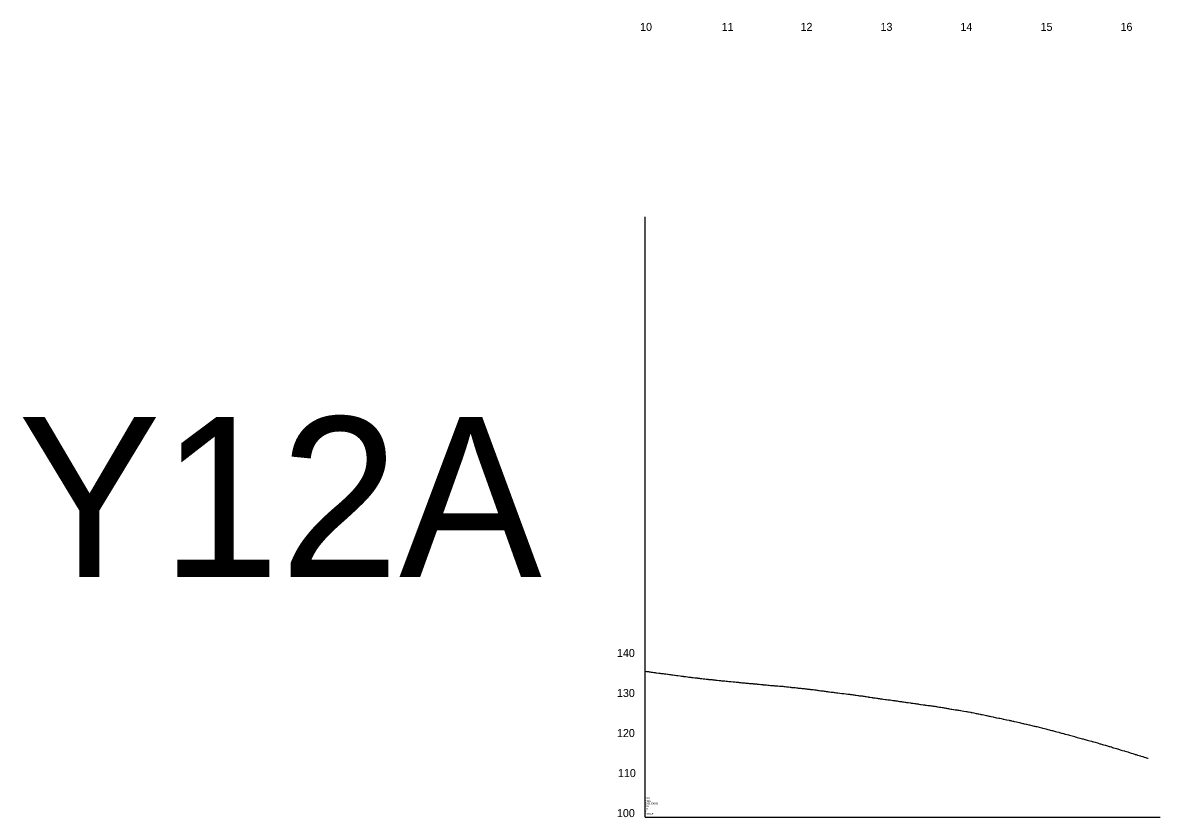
# Model space of a CAD drawing. Extents: x 1778432 to 1784301, y 601022 to 621789.
# Drawn here: x 1779365 to 1780786, y 605039 to 606032 of the extents above; entities that cross this region are included whole.
import ezdxf

# ---------------------------------------------------------------- set-up
doc = ezdxf.new("R2010")
doc.units = 0
for name, color, linetype in [('Exist Profile Cell', 7, 'Continuous'), ('Exist Vertical Profile Ground Line', 7, 'Continuous'), ('Exist Vertical Profile Horizontal Axis Label Major', 7, 'Continuous'), ('Exist Vertical Profile Vertical Axis Label', 7, 'Continuous'), ('Prop PFL Text', 7, 'Continuous')]:
    doc.layers.add(name, color=color, linetype=linetype)

msp = doc.modelspace()

# ---------------------------------------------------------------- linework, layer by layer
at = {"layer": 'Exist Profile Cell'}
for q in [(1780143, 605789.2), (1780786.2, 605039.2), (1780143, 605039.2)]:
    msp.add_line((1780143, 605039.2), q, dxfattribs=at)
at = {"layer": 'Exist Vertical Profile Ground Line'}
msp.add_lwpolyline([(1780143, 605221.6), (1780144.3, 605221.4), (1780145.2, 605221.3), (1780146.8, 605221.1), (1780147.9, 605220.9), (1780149.1, 605220.8), (1780150.2, 605220.6), (1780150.8, 605220.5), (1780151.9, 605220.4), (1780153.5, 605220.2), (1780154.2, 605220.1), (1780155.3, 605219.9), (1780156.2, 605219.8), (1780157.1, 605219.7), (1780159.7, 605219.3), (1780161.4, 605219.1), (1780162.4, 605219), (1780163.1, 605218.9), (1780164.2, 605218.8), (1780164.6, 605218.7), (1780165.3, 605218.6), (1780166.6, 605218.4), (1780168.6, 605218.2), (1780170.8, 605217.8), (1780171.4, 605217.8), (1780173.1, 605217.6), (1780173.9, 605217.4), (1780174.4, 605217.4), (1780175.7, 605217.2), (1780177.5, 605217), (1780179.3, 605216.7), (1780180.5, 605216.6), (1780182, 605216.4), (1780183.2, 605216.2), (1780183.5, 605216.2), (1780186.5, 605215.8), (1780188.3, 605215.6), (1780189.5, 605215.4), (1780190.1, 605215.3), (1780190.9, 605215.2), (1780191.9, 605215.1), (1780192.5, 605215), (1780193.8, 605214.9), (1780195.6, 605214.6), (1780197.3, 605214.4), (1780198.6, 605214.3), (1780199.4, 605214.2), (1780199.8, 605214.2), (1780200.9, 605214), (1780201.6, 605214), (1780202.7, 605213.8), (1780204.9, 605213.5), (1780206.3, 605213.3), (1780207.7, 605213.2), (1780208.1, 605213.1), (1780208.7, 605213.1), (1780209.9, 605212.9), (1780210.7, 605212.8), (1780211.7, 605212.6), (1780213.1, 605212.5), (1780213.7, 605212.4), (1780215.3, 605212.2), (1780216, 605212.1), (1780216.8, 605212.1), (1780217.1, 605212.1), (1780217.5, 605212), (1780218.9, 605211.8), (1780219.8, 605211.7), (1780220.7, 605211.7), (1780221.6, 605211.6), (1780221.9, 605211.5), (1780222.5, 605211.5), (1780222.8, 605211.4), (1780225, 605211.2), (1780225.9, 605211.1), (1780226.3, 605211.1), (1780227.2, 605211), (1780227.8, 605210.9), (1780228.9, 605210.8), (1780229.7, 605210.7), (1780230.7, 605210.6), (1780232, 605210.5), (1780232.7, 605210.4), (1780235.1, 605210.2), (1780236.8, 605210), (1780238.3, 605209.8), (1780239.5, 605209.7), (1780241.1, 605209.6), (1780242.2, 605209.5), (1780244.1, 605209.3), (1780245.8, 605209.1), (1780247.2, 605209), (1780247.6, 605208.9), (1780248.3, 605208.9), (1780249.4, 605208.7), (1780250.2, 605208.7), (1780252.6, 605208.4), (1780253.3, 605208.3), (1780255, 605208.2), (1780256.6, 605208), (1780256.9, 605208), (1780259.4, 605207.8), (1780260.1, 605207.7), (1780260.5, 605207.7), (1780261.2, 605207.6), (1780261.9, 605207.5), (1780262.4, 605207.4), (1780263.7, 605207.3), (1780265.6, 605207.1), (1780266.1, 605207.1), (1780267.3, 605207), (1780268.5, 605206.9), (1780269.1, 605206.8), (1780270, 605206.7), (1780270.9, 605206.6), (1780271.6, 605206.6), (1780272.7, 605206.5), (1780274.7, 605206.3), (1780276.3, 605206.2), (1780277.2, 605206.1), (1780277.7, 605206), (1780278.6, 605205.9), (1780279.9, 605205.8), (1780280.8, 605205.7), (1780281.7, 605205.7), (1780282.9, 605205.5), (1780283.5, 605205.4), (1780283.9, 605205.4), (1780285.3, 605205.3), (1780287.2, 605205.1), (1780288.3, 605205), (1780288.9, 605205), (1780290, 605204.9), (1780290.4, 605204.8), (1780291.5, 605204.7), (1780292.4, 605204.6), (1780293.1, 605204.6), (1780293.9, 605204.5), (1780294.2, 605204.5), (1780296.1, 605204.3), (1780297.8, 605204.1), (1780299.5, 605203.9), (1780300.1, 605203.9), (1780302.3, 605203.7), (1780303.4, 605203.6), (1780304.4, 605203.4), (1780305, 605203.4), (1780305.4, 605203.4), (1780306.6, 605203.3), (1780308.7, 605203.2), (1780310.6, 605203.1), (1780311.6, 605203), (1780312, 605203), (1780312.9, 605202.9), (1780313.9, 605202.8), (1780314.6, 605202.8), (1780316.1, 605202.6), (1780317.7, 605202.4), (1780319.2, 605202.3), (1780320.7, 605202.1), (1780321.7, 605202), (1780323.9, 605201.7), (1780324.6, 605201.6), (1780325.7, 605201.5), (1780326.5, 605201.5), (1780327.3, 605201.4), (1780327.6, 605201.3), (1780328.9, 605201.2), (1780330.1, 605201.1), (1780332, 605200.9), (1780332.8, 605200.8), (1780333.1, 605200.7), (1780333.9, 605200.6), (1780334.3, 605200.6), (1780335.4, 605200.5), (1780336.3, 605200.4), (1780337.1, 605200.3), (1780338.5, 605200.2), (1780339, 605200.2), (1780339.4, 605200.1), (1780340, 605200), (1780341.6, 605199.9), (1780342.6, 605199.8), (1780342.9, 605199.7), (1780343.9, 605199.6), (1780344.8, 605199.5), (1780345.6, 605199.4), (1780346.7, 605199.3), (1780347.5, 605199.2), (1780348.3, 605199.1), (1780349.5, 605199), (1780349.9, 605198.9), (1780351.2, 605198.8), (1780351.8, 605198.7), (1780352.7, 605198.6), (1780354.4, 605198.4), (1780355.1, 605198.3), (1780355.8, 605198.2), (1780357.3, 605198), (1780358, 605197.9), (1780359.4, 605197.7), (1780360, 605197.6), (1780360.6, 605197.6), (1780362.4, 605197.3), (1780364.3, 605197.1), (1780365.2, 605197), (1780366.2, 605196.8), (1780366.6, 605196.8), (1780367.6, 605196.7), (1780368.7, 605196.5), (1780370, 605196.4), (1780370.4, 605196.3), (1780371.7, 605196.1), (1780372.2, 605196.1), (1780372.6, 605196), (1780373, 605195.9), (1780375, 605195.6), (1780375.5, 605195.6), (1780377.3, 605195.3), (1780377.7, 605195.3), (1780378.7, 605195.1), (1780380.1, 605195), (1780381.8, 605194.7), (1780382.9, 605194.6), (1780383.4, 605194.6), (1780385.9, 605194.3), (1780388.4, 605193.9), (1780389.9, 605193.8), (1780390.8, 605193.7), (1780393.4, 605193.3), (1780394, 605193.3), (1780396.1, 605193), (1780398.3, 605192.8), (1780399.5, 605192.6), (1780400.3, 605192.5), (1780400.8, 605192.5), (1780401.4, 605192.4), (1780402.8, 605192.2), (1780403.8, 605192.1), (1780405.3, 605191.9), (1780406.4, 605191.7), (1780408.5, 605191.4), (1780408.8, 605191.4), (1780409.2, 605191.3), (1780410.7, 605191.1), (1780411.1, 605191.1), (1780411.4, 605191), (1780412.7, 605190.9), (1780413.9, 605190.7), (1780415, 605190.5), (1780416.2, 605190.3), (1780417.5, 605190.1), (1780417.9, 605190.1), (1780419, 605189.9), (1780420.9, 605189.6), (1780421.3, 605189.5), (1780421.9, 605189.4), (1780422.7, 605189.3), (1780423.7, 605189.1), (1780425.9, 605188.8), (1780426.5, 605188.8), (1780426.9, 605188.7), (1780427.3, 605188.6), (1780428.3, 605188.5), (1780430.1, 605188.3), (1780431.9, 605188), (1780433.2, 605187.8), (1780433.7, 605187.7), (1780434.3, 605187.6), (1780435.5, 605187.5), (1780436.4, 605187.3), (1780437.2, 605187.2), (1780438.3, 605187.1), (1780439.5, 605186.9), (1780442.7, 605186.5), (1780444.3, 605186.2), (1780446.1, 605186), (1780446.5, 605186), (1780447.9, 605185.8), (1780449, 605185.7), (1780450.7, 605185.4), (1780452.1, 605185.2), (1780454.3, 605184.9), (1780454.7, 605184.9), (1780455.3, 605184.8), (1780457.4, 605184.5), (1780458.7, 605184.3), (1780460.3, 605184), (1780461.6, 605183.9), (1780462.1, 605183.8), (1780462.9, 605183.7), (1780463.9, 605183.6), (1780464.7, 605183.4), (1780465.7, 605183.2), (1780467, 605183.1), (1780467.5, 605183), (1780467.9, 605183), (1780469.3, 605182.7), (1780471.2, 605182.5), (1780474.2, 605182.1), (1780475.2, 605181.9), (1780477.4, 605181.6), (1780479.2, 605181.4), (1780479.9, 605181.3), (1780480.5, 605181.2), (1780481.7, 605180.9), (1780483.3, 605180.8), (1780483.7, 605180.7), (1780484.8, 605180.5), (1780486.8, 605180.2), (1780487.5, 605180.1), (1780490, 605179.7), (1780490.7, 605179.6), (1780491.6, 605179.5), (1780492.5, 605179.4), (1780493.1, 605179.4), (1780494.3, 605179.2), (1780495.7, 605179), (1780496.1, 605179), (1780496.5, 605178.9), (1780498.4, 605178.7), (1780499.7, 605178.5), (1780501.5, 605178.2), (1780502.6, 605178.1), (1780503.8, 605177.9), (1780504.6, 605177.8), (1780505.8, 605177.7), (1780506.7, 605177.5), (1780508, 605177.3), (1780508.9, 605177.2), (1780510.3, 605176.9), (1780512.1, 605176.7), (1780514, 605176.4), (1780515.2, 605176.2), (1780516.2, 605176), (1780517.2, 605175.8), (1780518.4, 605175.6), (1780519.2, 605175.4), (1780520.3, 605175.2), (1780520.8, 605175.1), (1780521.6, 605175), (1780522.8, 605174.8), (1780524.7, 605174.4), (1780525.8, 605174.3), (1780527.8, 605174), (1780528.4, 605173.9), (1780530, 605173.6), (1780531, 605173.5), (1780532.5, 605173.2), (1780533.2, 605173.1), (1780534.1, 605173), (1780535.2, 605172.8), (1780536.6, 605172.6), (1780537.3, 605172.5), (1780538.8, 605172.2), (1780540.7, 605171.9), (1780543.6, 605171.4), (1780544.8, 605171.2), (1780546, 605171), (1780546.8, 605170.8), (1780549, 605170.4), (1780549.4, 605170.3), (1780549.9, 605170.2), (1780551.3, 605169.9), (1780553.2, 605169.5), (1780556.2, 605168.9), (1780557.1, 605168.7), (1780558.5, 605168.4), (1780559.4, 605168.3), (1780561.2, 605167.9), (1780561.9, 605167.7), (1780562.5, 605167.6), (1780563.8, 605167.4), (1780565.7, 605167), (1780567.3, 605166.7), (1780569.1, 605166.3), (1780569.5, 605166.2), (1780572, 605165.6), (1780573.5, 605165.3), (1780574.4, 605165.2), (1780575.1, 605165), (1780577.7, 605164.5), (1780578.4, 605164.3), (1780580.6, 605163.8), (1780581.7, 605163.6), (1780584.6, 605163), (1780585.1, 605162.9), (1780585.8, 605162.8), (1780587.8, 605162.4), (1780589.9, 605161.9), (1780590.6, 605161.8), (1780591, 605161.7), (1780594.1, 605161), (1780594.6, 605160.9), (1780597.3, 605160.3), (1780598.1, 605160.1), (1780599.4, 605159.9), (1780600.4, 605159.6), (1780602.2, 605159.2), (1780603, 605159.1), (1780603.6, 605159), (1780606.7, 605158.3), (1780608.3, 605157.9), (1780610.4, 605157.4), (1780613, 605156.8), (1780614.5, 605156.5), (1780615.5, 605156.3), (1780616.2, 605156.1), (1780618.7, 605155.6), (1780619.3, 605155.4), (1780621.9, 605154.8), (1780622.7, 605154.6), (1780625.7, 605153.9), (1780626.9, 605153.6), (1780628.8, 605153.1), (1780629.7, 605152.8), (1780630.9, 605152.7), (1780631.6, 605152.5), (1780632, 605152.4), (1780635.1, 605151.6), (1780638.3, 605150.8), (1780639.1, 605150.6), (1780641.5, 605150), (1780643.1, 605149.6), (1780644.6, 605149.2), (1780645.8, 605148.8), (1780647.7, 605148.4), (1780648.9, 605148.1), (1780650.9, 605147.5), (1780651.5, 605147.4), (1780654.1, 605146.7), (1780655.5, 605146.4), (1780657.2, 605146), (1780659.5, 605145.4), (1780660.4, 605145.1), (1780663, 605144.4), (1780663.7, 605144.2), (1780665.4, 605143.7), (1780666.7, 605143.4), (1780667.1, 605143.2), (1780667.7, 605143.1), (1780669.8, 605142.5), (1780671.8, 605142), (1780673, 605141.6), (1780676.1, 605140.8), (1780677.8, 605140.3), (1780679.3, 605139.9), (1780679.6, 605139.8), (1780680.1, 605139.7), (1780681.4, 605139.3), (1780682.5, 605139), (1780684.2, 605138.6), (1780685.6, 605138.2), (1780688.7, 605137.3), (1780690.1, 605137), (1780691.9, 605136.5), (1780692.5, 605136.4), (1780695.1, 605135.6), (1780696.5, 605135.2), (1780698.2, 605134.7), (1780700.5, 605134.1), (1780701, 605133.9), (1780701.4, 605133.8), (1780702.8, 605133.4), (1780704.7, 605132.9), (1780707.7, 605132), (1780708.8, 605131.7), (1780710.9, 605131.1), (1780711.7, 605130.9), (1780712.9, 605130.6), (1780714, 605130.2), (1780715.3, 605129.8), (1780717.2, 605129.3), (1780717.9, 605129.1), (1780720.3, 605128.4), (1780721.1, 605128.1), (1780722.4, 605127.7), (1780723.5, 605127.5), (1780725.2, 605127), (1780726.6, 605126.5), (1780727.7, 605126.1), (1780729.8, 605125.6), (1780731.5, 605125.1), (1780732.9, 605124.6), (1780733.3, 605124.5), (1780736.1, 605123.6), (1780737.5, 605123.2), (1780739.2, 605122.7), (1780741.5, 605122), (1780742, 605121.9), (1780742.4, 605121.7), (1780745.6, 605120.8), (1780748.7, 605119.8), (1780749.7, 605119.4), (1780751.8, 605118.8), (1780753.9, 605118.2), (1780754.5, 605118), (1780755, 605117.8), (1780756.3, 605117.4), (1780757.9, 605116.9), (1780758.2, 605116.8), (1780759.8, 605116.3), (1780761.6, 605115.8), (1780762, 605115.7), (1780764.5, 605114.9), (1780766.2, 605114.4), (1780767.6, 605114), (1780770.2, 605113.2), (1780770.6, 605113), (1780771.2, 605112.7)], dxfattribs=at)

# ---------------------------------------------------------------- texts
at = {"layer": 'Exist Profile Cell'}
for s, p in [('Y12A', (1780143, 605058.7)), ('RDY', (1780143, 605061.9)), ('2', (1780143, 605045.7)), ('1000.000000', (1780143, 605055.4)), ('100', (1780143, 605052.2)), ('10', (1780143, 605048.9)), ('NOGAP', (1780143, 605042.4))]:
    msp.add_text(s, height=2, dxfattribs=at).set_placement(p)
at = {"layer": 'Exist Vertical Profile Horizontal Axis Label Major'}
for s, p in [('10', (1780136.5, 606021.7)), ('11', (1780238.4, 606021.7)), ('12', (1780336.9, 606021.7)), ('13', (1780436.8, 606021.7)), ('14', (1780536.6, 606021.7)), ('15', (1780636.7, 606021.7)), ('16', (1780736.6, 606021.7))]:
    msp.add_text(s, height=10, dxfattribs=at).set_placement(p)
at = {"layer": 'Exist Vertical Profile Vertical Axis Label'}
for s, p in [('140', (1780107.6, 605239.4)), ('130', (1780107.6, 605189.4)), ('120', (1780107.6, 605139.4)), ('110', (1780108.8, 605089.4)), ('100', (1780107.6, 605039.4))]:
    msp.add_text(s, height=10, dxfattribs=at).set_placement(p)
at = {"layer": 'Prop PFL Text'}
msp.add_text('Y12A', height=200, dxfattribs=at).set_placement((1779359.5, 605339.2))

doc.saveas('drawing.dxf')
